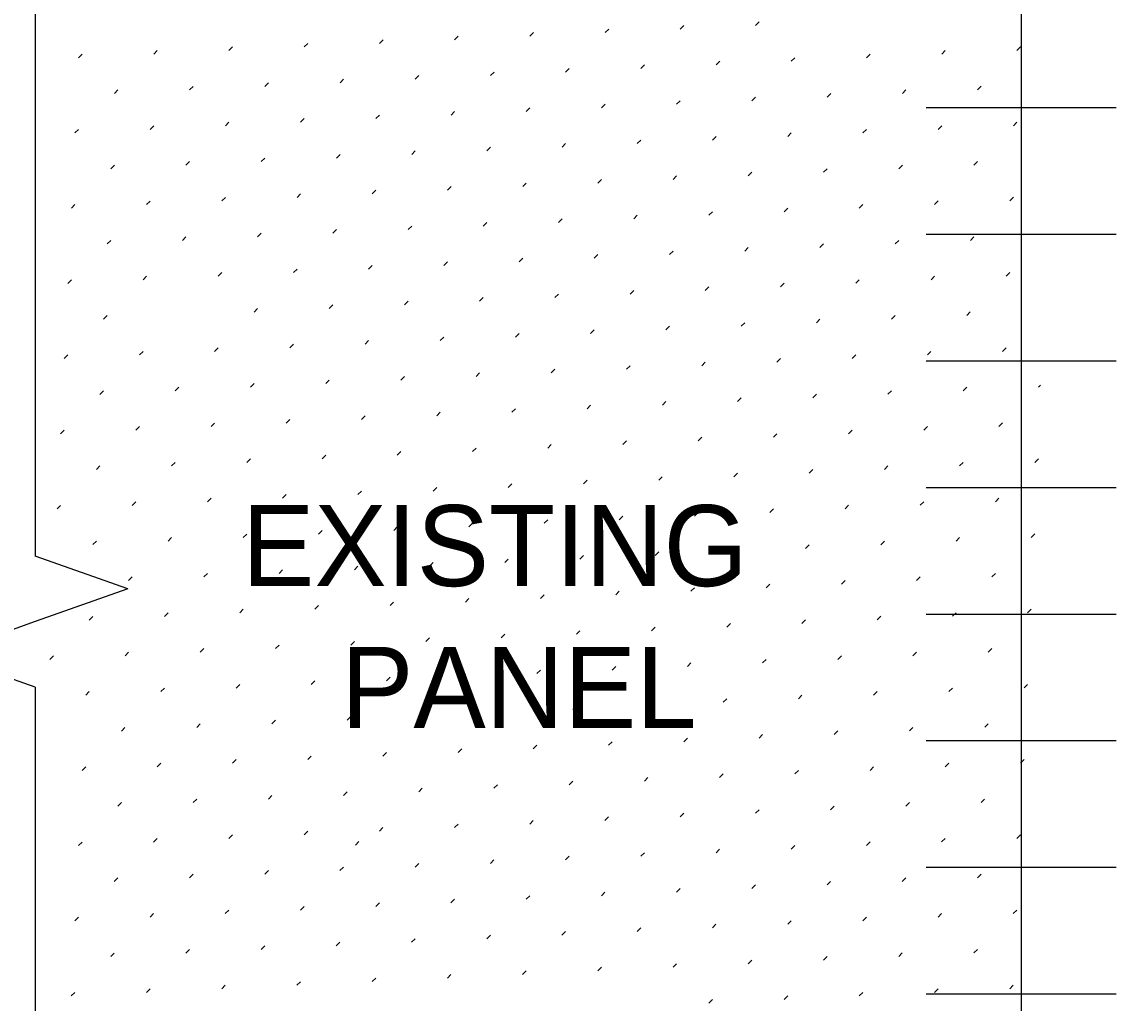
# Model space of a CAD drawing. Extents: x 49991.4 to 50021, y 49987.6 to 50011.4.
# Drawn here: x 50001.323 to 50002.404, y 49995.159 to 49996.127 of the extents above; entities that cross this region are included whole.
import ezdxf

# ---------------------------------------------------------------- set-up
doc = ezdxf.new("R2010")
doc.units = 0
for name, color, linetype in [('Level 1', 7, 'Continuous'), ('Level 10', 7, 'Continuous'), ('Level 2', 7, 'Continuous'), ('Level 4', 7, 'Continuous'), ('Level 6', 7, 'Continuous')]:
    doc.layers.add(name, color=color, linetype=linetype)

msp = doc.modelspace()

# ---------------------------------------------------------------- linework, layer by layer
at = {"layer": 'Level 1'}
msp.add_line((50002.3098, 49996.2901), (50002.3098, 49994.7903), dxfattribs=at)
at = {"layer": 'Level 10'}
for p, q in [((50001.8248, 49996.1132), (50001.8283, 49996.1168)), ((50001.899, 49996.1168), (50001.9026, 49996.1203)), ((50001.9733, 49996.1203), (50001.9768, 49996.1239)), ((50002.0475, 49996.1239), (50002.0511, 49996.1274)), ((50001.602, 49996.1026), (50001.6055, 49996.1061)), ((50001.6763, 49996.1061), (50001.6798, 49996.1097)), ((50001.7505, 49996.1097), (50001.754, 49996.1132)), ((50001.3792, 49996.092), (50001.3828, 49996.0955)), ((50001.4535, 49996.0955), (50001.457, 49996.0991)), ((50001.5277, 49996.0991), (50001.5313, 49996.1026)), ((50002.1571, 49996.092), (50002.1607, 49996.0956)), ((50002.2314, 49996.0956), (50002.2349, 49996.0991)), ((50002.3056, 49996.0991), (50002.3092, 49996.1027)), ((50001.9344, 49996.0814), (50001.9379, 49996.085)), ((50002.0086, 49996.085), (50002.0122, 49996.0885)), ((50002.0829, 49996.0885), (50002.0864, 49996.092)), ((50001.7116, 49996.0708), (50001.7151, 49996.0743)), ((50001.7859, 49996.0743), (50001.7894, 49996.0779)), ((50001.8601, 49996.0779), (50001.8637, 49996.0814)), ((50001.4889, 49996.0602), (50001.4924, 49996.0637)), ((50001.5631, 49996.0637), (50001.5666, 49996.0672)), ((50001.6374, 49996.0672), (50001.6409, 49996.0708)), ((50002.2667, 49996.0602), (50002.2703, 49996.0638)), ((50001.4146, 49996.0566), (50001.4181, 49996.0602)), ((50002.044, 49996.0496), (50002.0475, 49996.0531)), ((50002.1182, 49996.0531), (50002.1218, 49996.0567)), ((50002.1925, 49996.0567), (50002.196, 49996.0602)), ((50001.8212, 49996.039), (50001.8248, 49996.0425)), ((50001.8955, 49996.0425), (50001.899, 49996.0461)), ((50001.9697, 49996.0461), (50001.9733, 49996.0496)), ((50001.5985, 49996.0284), (50001.602, 49996.0319)), ((50001.6727, 49996.0319), (50001.6762, 49996.0354)), ((50001.747, 49996.0354), (50001.7505, 49996.039)), ((50001.3757, 49996.0177), (50001.3792, 49996.0213)), ((50001.45, 49996.0213), (50001.4535, 49996.0248)), ((50001.5242, 49996.0248), (50001.5277, 49996.0283)), ((50002.1536, 49996.0178), (50002.1571, 49996.0213)), ((50002.2278, 49996.0213), (50002.2314, 49996.0249)), ((50002.3021, 49996.0249), (50002.3056, 49996.0284)), ((50001.9308, 49996.0072), (50001.9344, 49996.0107)), ((50002.0051, 49996.0107), (50002.0086, 49996.0142)), ((50002.0793, 49996.0143), (50002.0829, 49996.0178)), ((50001.7081, 49995.9965), (50001.7116, 49996.0001)), ((50001.7823, 49996.0001), (50001.7859, 49996.0036)), ((50001.8566, 49996.0036), (50001.8601, 49996.0072)), ((50001.4853, 49995.9859), (50001.4888, 49995.9894)), ((50001.5596, 49995.9895), (50001.5631, 49995.993)), ((50001.6338, 49995.993), (50001.6374, 49995.9965)), ((50002.2632, 49995.986), (50002.2667, 49995.9895)), ((50001.4111, 49995.9824), (50001.4146, 49995.9859)), ((50002.0404, 49995.9754), (50002.044, 49995.9789)), ((50002.1147, 49995.9789), (50002.1182, 49995.9824)), ((50002.1889, 49995.9824), (50002.1925, 49995.986)), ((50001.8177, 49995.9647), (50001.8212, 49995.9683)), ((50001.8919, 49995.9683), (50001.8955, 49995.9718)), ((50001.9662, 49995.9718), (50001.9697, 49995.9753)), ((50001.5949, 49995.9541), (50001.5985, 49995.9576)), ((50001.6692, 49995.9576), (50001.6727, 49995.9612)), ((50001.7434, 49995.9612), (50001.747, 49995.9647)), ((50001.3722, 49995.9435), (50001.3757, 49995.947)), ((50001.4464, 49995.947), (50001.4499, 49995.9505)), ((50001.5207, 49995.9506), (50001.5242, 49995.9541)), ((50002.15, 49995.9435), (50002.1536, 49995.9471)), ((50002.2243, 49995.9471), (50002.2278, 49995.9506)), ((50002.2986, 49995.9506), (50002.3021, 49995.9542)), ((50001.9273, 49995.9329), (50001.9308, 49995.9364)), ((50002.0015, 49995.9365), (50002.0051, 49995.94)), ((50002.0758, 49995.94), (50002.0793, 49995.9435)), ((50001.6303, 49995.9187), (50001.6338, 49995.9223)), ((50001.7045, 49995.9223), (50001.7081, 49995.9258)), ((50001.7788, 49995.9258), (50001.7823, 49995.9294)), ((50001.853, 49995.9294), (50001.8566, 49995.9329)), ((50001.4075, 49995.9081), (50001.411, 49995.9117)), ((50001.4818, 49995.9117), (50001.4853, 49995.9152)), ((50001.556, 49995.9152), (50001.5596, 49995.9187)), ((50002.1854, 49995.9082), (50002.1889, 49995.9117)), ((50002.2597, 49995.9117), (50002.2632, 49995.9153)), ((50001.9626, 49995.8976), (50001.9662, 49995.9011)), ((50002.0369, 49995.9011), (50002.0404, 49995.9046)), ((50002.1111, 49995.9046), (50002.1147, 49995.9082)), ((50001.7399, 49995.8869), (50001.7434, 49995.8905)), ((50001.8141, 49995.8905), (50001.8177, 49995.894)), ((50001.8884, 49995.894), (50001.8919, 49995.8976)), ((50001.5171, 49995.8763), (50001.5207, 49995.8798)), ((50001.5914, 49995.8798), (50001.5949, 49995.8834)), ((50001.6656, 49995.8834), (50001.6692, 49995.8869)), ((50002.295, 49995.8764), (50002.2985, 49995.8799)), ((50001.3686, 49995.8692), (50001.3722, 49995.8728)), ((50001.4429, 49995.8728), (50001.4464, 49995.8763)), ((50002.0723, 49995.8657), (50002.0758, 49995.8693)), ((50002.1465, 49995.8693), (50002.15, 49995.8728)), ((50002.2208, 49995.8728), (50002.2243, 49995.8764)), ((50001.8495, 49995.8551), (50001.853, 49995.8587)), ((50001.9237, 49995.8587), (50001.9273, 49995.8622)), ((50001.998, 49995.8622), (50002.0015, 49995.8657)), ((50001.6267, 49995.8445), (50001.6303, 49995.848)), ((50001.701, 49995.848), (50001.7045, 49995.8516)), ((50001.7752, 49995.8516), (50001.7788, 49995.8551)), ((50001.404, 49995.8339), (50001.4075, 49995.8374)), ((50001.5525, 49995.8409), (50001.556, 49995.8445)), ((50002.1819, 49995.8339), (50002.1854, 49995.8375)), ((50002.2561, 49995.8375), (50002.2596, 49995.841)), ((50001.9591, 49995.8233), (50001.9626, 49995.8268)), ((50002.0334, 49995.8268), (50002.0369, 49995.8304)), ((50002.1076, 49995.8304), (50002.1111, 49995.8339)), ((50001.7363, 49995.8127), (50001.7399, 49995.8162)), ((50001.8106, 49995.8162), (50001.8141, 49995.8198)), ((50001.8848, 49995.8198), (50001.8884, 49995.8233)), ((50001.5136, 49995.802), (50001.5171, 49995.8056)), ((50001.5878, 49995.8056), (50001.5914, 49995.8091)), ((50001.6621, 49995.8091), (50001.6656, 49995.8127)), ((50002.2915, 49995.8021), (50002.295, 49995.8057)), ((50001.3651, 49995.795), (50001.3686, 49995.7985)), ((50001.4393, 49995.7985), (50001.4429, 49995.802)), ((50002.0687, 49995.7915), (50002.0722, 49995.795)), ((50002.143, 49995.795), (50002.1465, 49995.7986)), ((50002.2172, 49995.7986), (50002.2207, 49995.8021)), ((50001.8459, 49995.7809), (50001.8495, 49995.7844)), ((50001.9202, 49995.7844), (50001.9237, 49995.7879)), ((50001.9945, 49995.7879), (50001.998, 49995.7915)), ((50001.6232, 49995.7702), (50001.6267, 49995.7738)), ((50001.6974, 49995.7738), (50001.701, 49995.7773)), ((50001.7717, 49995.7773), (50001.7752, 49995.7809)), ((50001.4004, 49995.7596), (50001.404, 49995.7631)), ((50001.4747, 49995.7632), (50001.4782, 49995.7667)), ((50001.5489, 49995.7667), (50001.5525, 49995.7702)), ((50002.1783, 49995.7597), (50002.1819, 49995.7632)), ((50002.2526, 49995.7632), (50002.2561, 49995.7668)), ((50002.3268, 49995.7668), (50002.3288, 49995.7687)), ((50001.9556, 49995.7491), (50001.9591, 49995.7526)), ((50002.0298, 49995.7526), (50002.0333, 49995.7561)), ((50002.1041, 49995.7561), (50002.1076, 49995.7597)), ((50001.7328, 49995.7384), (50001.7363, 49995.742)), ((50001.807, 49995.742), (50001.8106, 49995.7455)), ((50001.8813, 49995.7455), (50001.8848, 49995.749)), ((50001.51, 49995.7278), (50001.5136, 49995.7313)), ((50001.5843, 49995.7313), (50001.5878, 49995.7349)), ((50001.6585, 49995.7349), (50001.6621, 49995.7384)), ((50002.2137, 49995.7243), (50002.2172, 49995.7279)), ((50002.2879, 49995.7279), (50002.2915, 49995.7314)), ((50001.3615, 49995.7207), (50001.3651, 49995.7242)), ((50001.4358, 49995.7243), (50001.4393, 49995.7278)), ((50001.9909, 49995.7137), (50001.9944, 49995.7172)), ((50002.0652, 49995.7172), (50002.0687, 49995.7208)), ((50002.1394, 49995.7208), (50002.143, 49995.7243)), ((50001.7682, 49995.7031), (50001.7717, 49995.7066)), ((50001.8424, 49995.7066), (50001.8459, 49995.7101)), ((50001.9167, 49995.7102), (50001.9202, 49995.7137)), ((50001.5454, 49995.6924), (50001.5489, 49995.696)), ((50001.6196, 49995.696), (50001.6232, 49995.6995)), ((50001.6939, 49995.6995), (50001.6974, 49995.7031)), ((50002.3233, 49995.6925), (50002.3268, 49995.696)), ((50001.3969, 49995.6854), (50001.4004, 49995.6889)), ((50001.4711, 49995.6889), (50001.4747, 49995.6924)), ((50002.1005, 49995.6819), (50002.1041, 49995.6854)), ((50002.1748, 49995.6854), (50002.1783, 49995.689)), ((50002.249, 49995.689), (50002.2526, 49995.6925)), ((50001.8778, 49995.6713), (50001.8813, 49995.6748)), ((50001.952, 49995.6748), (50001.9555, 49995.6783)), ((50002.0263, 49995.6783), (50002.0298, 49995.6819)), ((50001.655, 49995.6606), (50001.6585, 49995.6642)), ((50001.7293, 49995.6642), (50001.7328, 49995.6677)), ((50001.8035, 49995.6677), (50001.807, 49995.6712)), ((50001.4322, 49995.65), (50001.4358, 49995.6535)), ((50001.5065, 49995.6535), (50001.51, 49995.6571)), ((50001.5807, 49995.6571), (50001.5843, 49995.6606)), ((50002.2101, 49995.6501), (50002.2137, 49995.6536)), ((50002.2844, 49995.6536), (50002.2879, 49995.6571)), ((50001.358, 49995.6465), (50001.3615, 49995.65)), ((50001.9874, 49995.6394), (50001.9909, 49995.643)), ((50002.0616, 49995.643), (50002.0652, 49995.6465)), ((50002.1359, 49995.6465), (50002.1394, 49995.6501)), ((50001.7646, 49995.6288), (50001.7681, 49995.6324)), ((50001.8389, 49995.6324), (50001.8424, 49995.6359)), ((50001.9131, 49995.6359), (50001.9167, 49995.6394)), ((50001.5418, 49995.6182), (50001.5454, 49995.6217)), ((50001.6161, 49995.6217), (50001.6196, 49995.6253)), ((50001.6904, 49995.6253), (50001.6939, 49995.6288)), ((50002.3197, 49995.6183), (50002.3233, 49995.6218)), ((50001.3935, 49995.6113), (50001.3969, 49995.6146)), ((50001.4676, 49995.6146), (50001.4711, 49995.6182)), ((50002.097, 49995.6076), (50002.1005, 49995.6112)), ((50002.1712, 49995.6112), (50002.1748, 49995.6147)), ((50002.2455, 49995.6147), (50002.249, 49995.6183)), ((50001.8742, 49995.597), (50001.8778, 49995.6005)), ((50001.9485, 49995.6005), (50001.952, 49995.6041)), ((50002.0227, 49995.6041), (50002.0263, 49995.6076)), ((50001.6515, 49995.5864), (50001.655, 49995.5899)), ((50001.7257, 49995.5899), (50001.7292, 49995.5935)), ((50001.8, 49995.5935), (50001.8035, 49995.597)), ((50001.4287, 49995.5757), (50001.4322, 49995.5793)), ((50001.503, 49995.5793), (50001.5065, 49995.5828)), ((50001.5772, 49995.5828), (50001.5807, 49995.5864)), ((50002.2066, 49995.5758), (50002.2101, 49995.5794)), ((50002.2808, 49995.5794), (50002.2844, 49995.5829)), ((50001.9838, 49995.5652), (50001.9874, 49995.5687)), ((50002.0581, 49995.5687), (50002.0616, 49995.5723)), ((50002.1323, 49995.5723), (50002.1359, 49995.5758)), ((50001.7611, 49995.5546), (50001.7646, 49995.5581)), ((50001.8353, 49995.5581), (50001.8389, 49995.5616)), ((50001.9096, 49995.5616), (50001.9131, 49995.5652)), ((50001.5383, 49995.5439), (50001.5418, 49995.5475)), ((50001.6126, 49995.5475), (50001.6161, 49995.551)), ((50001.6868, 49995.551), (50001.6903, 49995.5546)), ((50002.3162, 49995.544), (50002.3197, 49995.5475)), ((50001.3898, 49995.5368), (50001.3933, 49995.5404)), ((50001.4641, 49995.5404), (50001.4676, 49995.5439)), ((50002.0192, 49995.5298), (50002.0227, 49995.5334)), ((50002.0934, 49995.5334), (50002.097, 49995.5369)), ((50002.1677, 49995.5369), (50002.1712, 49995.5405)), ((50002.2419, 49995.5405), (50002.2455, 49995.544)), ((50001.7964, 49995.5192), (50001.8, 49995.5227)), ((50001.8707, 49995.5227), (50001.8742, 49995.5263)), ((50001.9449, 49995.5263), (50001.9485, 49995.5298)), ((50001.5737, 49995.5086), (50001.5772, 49995.5121)), ((50001.6479, 49995.5121), (50001.6515, 49995.5157)), ((50001.7222, 49995.5157), (50001.7257, 49995.5192)), ((50001.3509, 49995.498), (50001.3544, 49995.5015)), ((50001.4252, 49995.5015), (50001.4287, 49995.505)), ((50001.4994, 49995.505), (50001.5029, 49995.5086)), ((50002.1288, 49995.498), (50002.1323, 49995.5016)), ((50002.203, 49995.5016), (50002.2066, 49995.5051)), ((50002.2773, 49995.5051), (50002.2808, 49995.5086)), ((50001.906, 49995.4874), (50001.9096, 49995.4909)), ((50001.9803, 49995.4909), (50001.9838, 49995.4945)), ((50002.0545, 49995.4945), (50002.0581, 49995.498)), ((50001.6833, 49995.4768), (50001.6868, 49995.4803)), ((50001.7575, 49995.4803), (50001.7611, 49995.4838)), ((50001.8318, 49995.4839), (50001.8353, 49995.4874)), ((50001.4605, 49995.4661), (50001.464, 49995.4697)), ((50001.5348, 49995.4697), (50001.5383, 49995.4732)), ((50001.609, 49995.4732), (50001.6126, 49995.4768)), ((50002.2384, 49995.4662), (50002.2419, 49995.4697)), ((50002.3127, 49995.4698), (50002.3162, 49995.4733)), ((50001.3863, 49995.4626), (50001.3898, 49995.4661)), ((50002.0156, 49995.4556), (50002.0192, 49995.4591)), ((50002.0899, 49995.4591), (50002.0934, 49995.4627)), ((50002.1641, 49995.4627), (50002.1677, 49995.4662)), ((50001.7929, 49995.445), (50001.7964, 49995.4485)), ((50001.8671, 49995.4485), (50001.8707, 49995.452)), ((50001.9414, 49995.452), (50001.9449, 49995.4556)), ((50001.5701, 49995.4343), (50001.5737, 49995.4379)), ((50001.6444, 49995.4379), (50001.6479, 49995.4414)), ((50001.7186, 49995.4414), (50001.7222, 49995.4449)), ((50001.4216, 49995.4272), (50001.4251, 49995.4308)), ((50001.4959, 49995.4308), (50001.4994, 49995.4343)), ((50002.1252, 49995.4238), (50002.1288, 49995.4273)), ((50002.1995, 49995.4273), (50002.203, 49995.4308)), ((50002.2738, 49995.4309), (50002.2773, 49995.4344)), ((50001.9025, 49995.4131), (50001.906, 49995.4167)), ((50001.9767, 49995.4167), (50001.9803, 49995.4202)), ((50002.051, 49995.4202), (50002.0545, 49995.4238)), ((50001.6797, 49995.4025), (50001.6833, 49995.406)), ((50001.754, 49995.4061), (50001.7575, 49995.4096)), ((50001.8282, 49995.4096), (50001.8318, 49995.4131)), ((50001.457, 49995.3919), (50001.4605, 49995.3954)), ((50001.5312, 49995.3954), (50001.5348, 49995.399)), ((50001.6055, 49995.399), (50001.609, 49995.4025)), ((50002.2349, 49995.392), (50002.2384, 49995.3955)), ((50002.3091, 49995.3955), (50002.3126, 49995.399)), ((50001.3827, 49995.3883), (50001.3863, 49995.3919)), ((50002.0121, 49995.3813), (50002.0156, 49995.3849)), ((50002.0863, 49995.3849), (50002.0899, 49995.3884)), ((50002.1606, 49995.3884), (50002.1641, 49995.3919)), ((50001.7893, 49995.3707), (50001.7929, 49995.3742)), ((50001.8636, 49995.3742), (50001.8671, 49995.3778)), ((50001.9378, 49995.3778), (50001.9414, 49995.3813)), ((50001.5666, 49995.3601), (50001.5701, 49995.3636)), ((50001.6408, 49995.3636), (50001.6444, 49995.3672)), ((50001.7151, 49995.3672), (50001.7186, 49995.3707)), ((50001.4181, 49995.353), (50001.4216, 49995.3565)), ((50001.4923, 49995.3565), (50001.4959, 49995.3601)), ((50002.1217, 49995.3495), (50002.1252, 49995.3531)), ((50002.196, 49995.3531), (50002.1995, 49995.3566)), ((50002.2702, 49995.3566), (50002.2737, 49995.3601)), ((50001.8989, 49995.3389), (50001.9025, 49995.3424)), ((50001.9732, 49995.3424), (50001.9767, 49995.346)), ((50002.0475, 49995.346), (50002.051, 49995.3495)), ((50001.6019, 49995.3247), (50001.6055, 49995.3283)), ((50001.6762, 49995.3283), (50001.6797, 49995.3318)), ((50001.7504, 49995.3318), (50001.754, 49995.3353)), ((50001.8247, 49995.3353), (50001.8282, 49995.3389)), ((50001.3792, 49995.3141), (50001.3827, 49995.3176)), ((50001.4534, 49995.3176), (50001.457, 49995.3212)), ((50001.5277, 49995.3212), (50001.5312, 49995.3247)), ((50001.6525, 49995.3146), (50001.656, 49995.3182)), ((50002.1571, 49995.3142), (50002.1606, 49995.3177)), ((50002.2313, 49995.3177), (50002.2348, 49995.3212)), ((50002.3056, 49995.3212), (50002.3091, 49995.3248)), ((50001.9343, 49995.3035), (50001.9378, 49995.3071)), ((50002.0086, 49995.3071), (50002.0121, 49995.3106)), ((50002.0828, 49995.3106), (50002.0863, 49995.3142)), ((50001.7115, 49995.2929), (50001.7151, 49995.2964)), ((50001.7858, 49995.2964), (50001.7893, 49995.3)), ((50001.86, 49995.3), (50001.8636, 49995.3035)), ((50001.4888, 49995.2823), (50001.4923, 49995.2858)), ((50001.563, 49995.2858), (50001.5666, 49995.2894)), ((50001.6373, 49995.2894), (50001.6408, 49995.2929)), ((50002.2667, 49995.2823), (50002.2702, 49995.2859)), ((50001.4145, 49995.2787), (50001.4181, 49995.2823)), ((50002.0439, 49995.2717), (50002.0474, 49995.2753)), ((50002.1182, 49995.2753), (50002.1217, 49995.2788)), ((50002.1924, 49995.2788), (50002.196, 49995.2823)), ((50001.8211, 49995.2611), (50001.8247, 49995.2646)), ((50001.8954, 49995.2646), (50001.8989, 49995.2682)), ((50001.9697, 49995.2682), (50001.9732, 49995.2717)), ((50001.5984, 49995.2505), (50001.6019, 49995.254)), ((50001.6726, 49995.254), (50001.6762, 49995.2575)), ((50001.7469, 49995.2575), (50001.7504, 49995.2611)), ((50001.3756, 49995.2398), (50001.3792, 49995.2434)), ((50001.4499, 49995.2434), (50001.4534, 49995.2469)), ((50001.5241, 49995.2469), (50001.5277, 49995.2505)), ((50002.1535, 49995.2399), (50002.1571, 49995.2434)), ((50002.2278, 49995.2434), (50002.2313, 49995.247)), ((50002.302, 49995.247), (50002.3056, 49995.2505)), ((50001.9308, 49995.2293), (50001.9343, 49995.2328)), ((50002.005, 49995.2328), (50002.0085, 49995.2364)), ((50002.0793, 49995.2364), (50002.0828, 49995.2399)), ((50001.708, 49995.2187), (50001.7115, 49995.2222)), ((50001.7823, 49995.2222), (50001.7858, 49995.2257)), ((50001.8565, 49995.2257), (50001.86, 49995.2293)), ((50001.4852, 49995.208), (50001.4888, 49995.2116)), ((50001.5595, 49995.2116), (50001.563, 49995.2151)), ((50001.6337, 49995.2151), (50001.6373, 49995.2186)), ((50002.2631, 49995.2081), (50002.2667, 49995.2116)), ((50001.411, 49995.2045), (50001.4145, 49995.208)), ((50002.0404, 49995.1975), (50002.0439, 49995.201)), ((50002.1146, 49995.201), (50002.1182, 49995.2045)), ((50002.1889, 49995.2046), (50002.1924, 49995.2081)), ((50001.8176, 49995.1868), (50001.8211, 49995.1904)), ((50001.8919, 49995.1904), (50001.8954, 49995.1939)), ((50001.9661, 49995.1939), (50001.9696, 49995.1975)), ((50001.5948, 49995.1762), (50001.5984, 49995.1797)), ((50001.6691, 49995.1798), (50001.6726, 49995.1833)), ((50001.7434, 49995.1833), (50001.7469, 49995.1868)), ((50001.3721, 49995.1656), (50001.3756, 49995.1691)), ((50001.4463, 49995.1691), (50001.4499, 49995.1727)), ((50001.5206, 49995.1727), (50001.5241, 49995.1762)), ((50002.15, 49995.1657), (50002.1535, 49995.1692)), ((50002.2242, 49995.1692), (50002.2278, 49995.1727)), ((50002.2985, 49995.1727), (50002.302, 49995.1763)), ((50002.0015, 49995.1586), (50002.005, 49995.1621)), ((50002.0757, 49995.1621), (50002.0793, 49995.1656))]:
    msp.add_line(p, q, dxfattribs=at)
at = {"layer": 'Level 4'}
for p, q in [((50002.216, 49996.0427), (50002.4035, 49996.0427)), ((50002.216, 49995.9177), (50002.4035, 49995.9177)), ((50002.216, 49995.7927), (50002.4035, 49995.7927)), ((50002.216, 49995.6677), (50002.4035, 49995.6677)), ((50002.216, 49995.5427), (50002.4035, 49995.5427)), ((50002.216, 49995.4177), (50002.4035, 49995.4177)), ((50002.216, 49995.2927), (50002.4035, 49995.2927)), ((50002.216, 49995.1677), (50002.4035, 49995.1677))]:
    msp.add_line(p, q, dxfattribs=at)
at = {"layer": 'Level 6'}
for p, q in [((50001.3364, 49996.9704), (50001.3364, 49995.6)), ((50001.4278, 49995.5676), (50001.3364, 49995.6)), ((50001.4278, 49995.5676), (50001.3364, 49995.5352)), ((50001.3364, 49995.5352), (50001.245, 49995.5028)), ((50001.3364, 49995.4704), (50001.245, 49995.5028)), ((50001.3364, 49995.4704), (50001.3364, 49994.1903))]:
    msp.add_line(p, q, dxfattribs=at)

# ---------------------------------------------------------------- texts
at = {"layer": 'Level 2'}
for s, p in [('EXISTING', (50001.5407, 49995.5703)), ('PANEL', (50001.6385, 49995.4303))]:
    msp.add_text(s, height=0.08, dxfattribs=at).set_placement(p)

doc.saveas('drawing.dxf')
